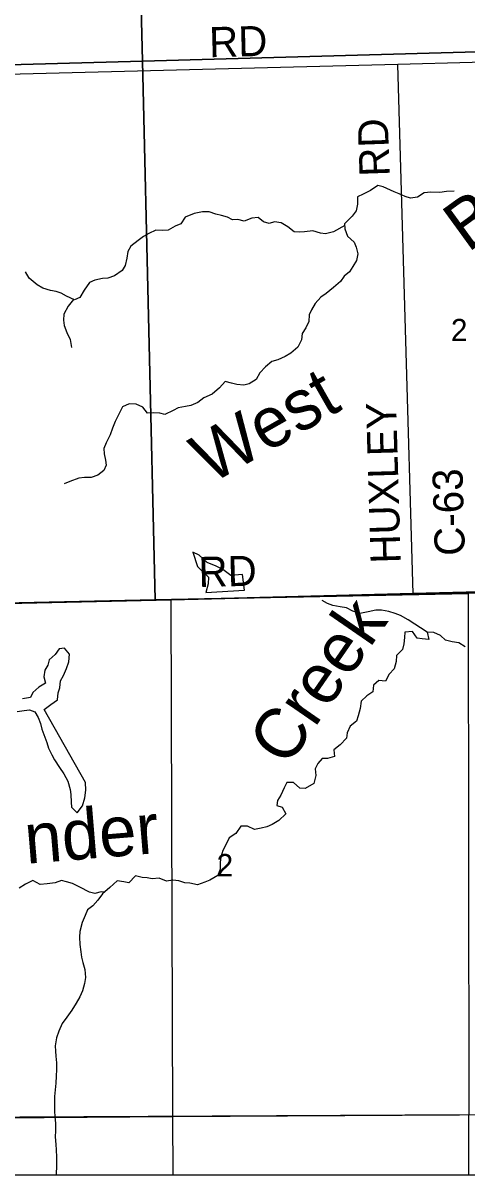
# Model space of a CAD drawing. Extents: x 0 to 34, y 0 to 22.
# Drawn here: x 8.101 to 8.938, y 14.007 to 16.179 of the extents above; entities that cross this region are included whole.
import ezdxf

# ---------------------------------------------------------------- set-up
doc = ezdxf.new("R2010")
doc.units = 0
for name, color, linetype in [('GM_X_Corporation', 7, 'Continuous'), ('GM_X_County_Road', 7, 'Continuous'), ('GM_X_County_Road_Text', 7, 'Continuous'), ('GM_X_Minor_Lake', 7, 'Continuous'), ('GM_X_Minor_River', 7, 'Continuous'), ('GM_X_Minor_River_Text', 7, 'Continuous'), ('GM_X_Section_Text', 7, 'Continuous'), ('GM_X_Township_Road', 7, 'Continuous')]:
    doc.layers.add(name, color=color, linetype=linetype)

msp = doc.modelspace()

# ---------------------------------------------------------------- linework, layer by layer
at = {"layer": 'GM_X_Corporation'}
msp.add_lwpolyline([(7.283, 17.3071), (7.2872, 17.1772), (7.2911, 17.0516), (7.2943, 16.935), (7.2998, 16.7507), (7.3046, 16.5913), (7.3049, 16.5704), (7.3097, 16.0633), (7.3129, 15.9614), (7.3375, 15.0689), (8.3803, 15.0917), (8.8365, 15.1033), (9.7895, 15.1275), (9.7895, 20.2375)], dxfattribs=at)
for points in [[(9.3117, 17.1675), (9.3404, 16.1359), (8.3266, 16.1074), (8.3006, 17.1406)], [(8.3006, 17.1406), (8.3266, 16.1074), (7.3183, 16.0795), (7.3111, 16.3358), (7.2941, 16.9623), (7.2894, 17.115)], [(8.3266, 16.1074), (9.3404, 16.1359), (9.3634, 15.1175), (8.9404, 15.1037), (8.3505, 15.0912)], [(7.3183, 16.0795), (8.3266, 16.1074), (8.3505, 15.0912), (7.8364, 15.0804), (7.3467, 15.0701), (7.331, 15.7019)], [(3.7367, 14.0069), (9.7895, 14.0069), (9.7895, 15.1275), (8.8365, 15.1033), (8.3803, 15.0917), (7.3375, 15.0689), (7.3134, 15.0684), (6.0746, 15.0468), (5.7825, 15.0418), (5.1362, 15.0301), (3.7218, 15.0051), (3.7359, 14.0555)], [(8.9404, 15.1037), (8.9421, 14.1205), (7.8527, 14.1143), (7.8364, 15.0804), (8.3505, 15.0912)], [(7.8543, 14.0069), (8.9421, 14.0069), (8.9421, 14.1205), (7.8527, 14.1143)]]:
    msp.add_lwpolyline(points, close=True, dxfattribs=at)
at = {"layer": 'GM_X_County_Road'}
for q in [(8.8082, 16.1011), (9.7895, 15.1269)]:
    msp.add_line((8.8367, 15.1028), q, dxfattribs=at)
for points in [[(9.7895, 16.1277), (8.8082, 16.1011), (7.3099, 16.0628)], [(7.3377, 15.0683), (8.3805, 15.0912), (8.8367, 15.1028)], [(7.332, 14.1088), (8.3836, 14.1171), (9.7895, 14.1254)]]:
    msp.add_lwpolyline(points, dxfattribs=at)
at = {"layer": 'GM_X_Minor_Lake'}
for points in [[(8.5187, 15.1098), (8.5152, 15.139), (8.4929, 15.1374), (8.4782, 15.1489), (8.4652, 15.1552), (8.4488, 15.1621), (8.4334, 15.1758), (8.4212, 15.1813), (8.4304, 15.1541), (8.4512, 15.1344), (8.4507, 15.1215), (8.4457, 15.1054)], [(8.4457, 15.1054), (8.5187, 15.1098)], [(8.1414, 14.8847), (8.1537, 14.894), (8.1664, 14.9026), (8.1677, 14.9159), (8.1709, 14.9255), (8.1722, 14.9388), (8.1773, 14.9488), (8.1835, 14.9622), (8.1875, 14.9748), (8.1887, 14.9889), (8.1794, 15.0001), (8.1692, 14.9988), (8.1618, 14.9884), (8.1503, 14.9783), (8.1478, 14.9684), (8.1423, 14.9588), (8.1406, 14.9466), (8.1439, 14.9345), (8.1311, 14.927), (8.1196, 14.9169), (8.1152, 14.9074), (8.1005, 14.9048)], [(8.0903, 14.8807), (8.1035, 14.8825), (8.1134, 14.8838), (8.1233, 14.8805), (8.1299, 14.8697), (8.1343, 14.8583), (8.1368, 14.8474), (8.1427, 14.8327), (8.1463, 14.8225), (8.1495, 14.8119), (8.1555, 14.7995), (8.1609, 14.7897), (8.1699, 14.7754), (8.1781, 14.7634), (8.1859, 14.7495), (8.1904, 14.7337), (8.1913, 14.7242), (8.192, 14.7098), (8.1925, 14.7003), (8.2033, 14.6895), (8.2137, 14.7033), (8.218, 14.7182), (8.2196, 14.7323), (8.2193, 14.7468)], [(8.2193, 14.7468), (8.1414, 14.8847)]]:
    msp.add_lwpolyline(points, dxfattribs=at)
at = {"layer": 'GM_X_Minor_River'}
for points in [[(8.9144, 15.8625), (8.9, 15.8619), (8.8872, 15.8597), (8.8701, 15.8606), (8.858, 15.8588), (8.8453, 15.8506), (8.8321, 15.8488), (8.8218, 15.852), (8.8107, 15.8572), (8.8012, 15.8608), (8.7805, 15.8706), (8.7702, 15.8727), (8.7568, 15.8634), (8.7425, 15.8566), (8.732, 15.8515), (8.7322, 15.8378), (8.7295, 15.8249), (8.7221, 15.8152), (8.7075, 15.8009), (8.7081, 15.7914), (8.7129, 15.7771), (8.7256, 15.7663), (8.7292, 15.7565), (8.7325, 15.744), (8.73, 15.7314), (8.7231, 15.7203), (8.7168, 15.7103), (8.7071, 15.7017), (8.6997, 15.6921), (8.687, 15.6805), (8.6728, 15.6692), (8.6631, 15.6626), (8.652, 15.6506), (8.6454, 15.6387), (8.641, 15.6291), (8.6405, 15.6162), (8.6346, 15.6047), (8.6276, 15.5935), (8.6267, 15.5817), (8.6194, 15.5683), (8.6064, 15.5566), (8.5955, 15.5504), (8.5816, 15.5444), (8.5706, 15.5408), (8.5583, 15.5307), (8.5479, 15.5198), (8.5406, 15.5068), (8.5279, 15.499), (8.5177, 15.4965), (8.5044, 15.4978), (8.4945, 15.5002), (8.4823, 15.5034), (8.4715, 15.4914), (8.4581, 15.4794), (8.442, 15.4723), (8.4311, 15.4637), (8.418, 15.4581), (8.4074, 15.4564), (8.3938, 15.4539), (8.3841, 15.4484), (8.369, 15.4413), (8.3595, 15.4437), (8.3466, 15.4443), (8.336, 15.4433), (8.3275, 15.4549), (8.3149, 15.4608), (8.3012, 15.4613), (8.2888, 15.4553), (8.2811, 15.4404), (8.2753, 15.4277), (8.2699, 15.4155), (8.2655, 15.4029), (8.2579, 15.3879), (8.2535, 15.3772), (8.2545, 15.3666), (8.257, 15.3552), (8.2579, 15.3454), (8.2535, 15.3354), (8.2423, 15.3264), (8.2299, 15.3224), (8.2174, 15.3222), (8.2068, 15.3208), (8.1895, 15.3144), (8.179, 15.3104)], [(8.7078, 15.7972), (8.687, 15.7857), (8.6719, 15.7816), (8.662, 15.7833), (8.6479, 15.7872), (8.6321, 15.7854), (8.6222, 15.7849), (8.6123, 15.7858), (8.6004, 15.7951), (8.5882, 15.8028), (8.5752, 15.8045), (8.5655, 15.8013), (8.5548, 15.8045), (8.5448, 15.8126), (8.5327, 15.8113), (8.518, 15.8057), (8.5062, 15.8089), (8.4964, 15.8083), (8.4868, 15.8135), (8.4758, 15.8163), (8.4651, 15.8187), (8.4521, 15.8231), (8.4396, 15.8232), (8.4238, 15.8202), (8.4069, 15.8135), (8.3991, 15.8004), (8.3879, 15.7964), (8.3751, 15.7889), (8.3638, 15.788), (8.352, 15.7889), (8.3385, 15.7826), (8.3283, 15.777), (8.3186, 15.7689), (8.3048, 15.7584), (8.2989, 15.7484), (8.2969, 15.7358), (8.2937, 15.7221), (8.2882, 15.7125), (8.274, 15.7027), (8.2612, 15.6983), (8.251, 15.6973), (8.2367, 15.6944), (8.2265, 15.6897), (8.2165, 15.6758), (8.2081, 15.6616), (8.1983, 15.6572), (8.1834, 15.6642), (8.1735, 15.6697), (8.1639, 15.6729), (8.1533, 15.6746), (8.1384, 15.6796), (8.1281, 15.6855), (8.1131, 15.6982), (8.1057, 15.7098)], [(8.1964, 15.6581), (8.1864, 15.6452), (8.1784, 15.6303), (8.1778, 15.6189), (8.1791, 15.609), (8.1839, 15.5958), (8.1902, 15.5822), (8.1928, 15.5675)], [(8.8631, 15.0305), (8.8274, 15.0541), (8.8133, 15.0618), (8.803, 15.0658), (8.7912, 15.0694), (8.7771, 15.0721), (8.7665, 15.0723), (8.7521, 15.069), (8.7363, 15.0657), (8.7233, 15.0704), (8.7115, 15.0762), (8.6993, 15.0783), (8.6852, 15.081), (8.6757, 15.0847), (8.6654, 15.0905)], [(8.9352, 15.0029), (8.9233, 15.0107), (8.9104, 15.012), (8.8979, 15.0152), (8.8882, 15.0241), (8.876, 15.0299), (8.8631, 15.0305), (8.8668, 15.0168), (8.8542, 15.0178), (8.8447, 15.0191), (8.8354, 15.0315), (8.8214, 15.0308), (8.8205, 15.0205), (8.8192, 15.0087), (8.8167, 14.9981), (8.8056, 14.9864), (8.805, 14.9754), (8.8011, 14.9613), (8.7918, 14.9512), (8.7849, 14.9382), (8.7723, 14.9391), (8.7623, 14.9306), (8.761, 14.918), (8.7498, 14.9102), (8.7386, 14.9001), (8.7369, 14.8868), (8.7334, 14.8727), (8.7298, 14.8627), (8.7179, 14.853), (8.7128, 14.8404), (8.7115, 14.8308), (8.6992, 14.8181), (8.6876, 14.8084), (8.6886, 14.7962), (8.6754, 14.7922), (8.6656, 14.7924), (8.6574, 14.7827), (8.6519, 14.7727), (8.6537, 14.7602), (8.6498, 14.745), (8.6333, 14.7359), (8.623, 14.7365), (8.6115, 14.7473), (8.599, 14.7471), (8.5938, 14.7371), (8.5877, 14.7229), (8.5814, 14.7129), (8.5797, 14.7034), (8.59, 14.7005), (8.597, 14.6881), (8.5836, 14.6754), (8.5709, 14.6679), (8.5611, 14.6635), (8.5505, 14.6607), (8.5377, 14.6585), (8.5247, 14.6648), (8.5118, 14.6645), (8.5026, 14.651), (8.4899, 14.6428), (8.4829, 14.6283), (8.4782, 14.6187), (8.4746, 14.6061), (8.4729, 14.5965), (8.4728, 14.5833), (8.4685, 14.5714), (8.4538, 14.5631), (8.4441, 14.5592), (8.4301, 14.5543), (8.4157, 14.5571), (8.4062, 14.5577), (8.3951, 14.5617), (8.3837, 14.563), (8.3717, 14.5612), (8.3579, 14.5667), (8.3451, 14.5653), (8.3356, 14.567), (8.3257, 14.5676), (8.3131, 14.5711), (8.3009, 14.558), (8.2914, 14.5597), (8.2788, 14.5617), (8.265, 14.5493), (8.2509, 14.5369), (8.2424, 14.5254), (8.2331, 14.5145), (8.223, 14.5071), (8.2186, 14.4964), (8.2128, 14.483), (8.2082, 14.4658), (8.2077, 14.4552), (8.2083, 14.4415), (8.2101, 14.4275), (8.2118, 14.4177), (8.2142, 14.4078), (8.2179, 14.3946), (8.2193, 14.3791), (8.2172, 14.368), (8.2133, 14.3543), (8.2082, 14.3428), (8.2012, 14.3309), (8.1935, 14.3178)], [(8.2548, 14.5403), (8.2489, 14.5407), (8.2365, 14.5374), (8.2266, 14.5403), (8.2082, 14.5498), (8.1944, 14.5564), (8.1834, 14.5599), (8.1739, 14.5621), (8.1618, 14.558), (8.1471, 14.5562), (8.1338, 14.5548), (8.1201, 14.5622), (8.1062, 14.5555), (8.0942, 14.5476)], [(8.1935, 14.3178), (8.1839, 14.3047), (8.1751, 14.2924), (8.1689, 14.2782), (8.1646, 14.2652), (8.1622, 14.2504), (8.1624, 14.2401), (8.1633, 14.2306), (8.1643, 14.2185), (8.1642, 14.2056), (8.1636, 14.1934), (8.1631, 14.1797), (8.1618, 14.1672), (8.1609, 14.155), (8.1608, 14.1402), (8.1607, 14.1273), (8.1613, 14.117), (8.1626, 14.1037), (8.1625, 14.0901), (8.1616, 14.0787), (8.163, 14.0643), (8.1639, 14.0544), (8.1646, 14.0404), (8.1645, 14.0255), (8.1637, 14.0069), (8.1637, 14.0069)]]:
    msp.add_lwpolyline(points, dxfattribs=at)
at = {"layer": 'GM_X_Township_Road'}
for p, q in [((8.3818, 14.6795), (8.3805, 15.0912)), ((8.3836, 14.1171), (8.3818, 14.6795)), ((8.3843, 14.0069), (8.3836, 14.1171))]:
    msp.add_line(p, q, dxfattribs=at)

# ---------------------------------------------------------------- texts
at = {"layer": 'GM_X_County_Road_Text'}
for s, rotation, p in [('RD', 1.4806, (8.4529, 16.1147)), ('RD', 91.9757, (8.7928, 15.8907)), ('HUXLEY', 91.6703, (8.8136, 15.1608)), ('C-63', 91.7153, (8.9347, 15.1753)), ('RD', 1.4825, (8.4329, 15.1155))]:
    msp.add_text(s, height=0.05682, rotation=rotation, dxfattribs=at).set_placement(p)
at = {"layer": 'GM_X_Minor_River_Text'}
for s, rotation, p in [('Branch', 35.9921, (8.9401, 15.7452)), ('West', 29.724, (8.4548, 15.3085)), ('Creek', 55.3631, (8.5991, 14.7736)), ('nder', 4.7074, (8.1076, 14.5936))]:
    msp.add_text(s, height=0.09473, rotation=rotation, dxfattribs=at).set_placement(p)
at = {"layer": 'GM_X_Section_Text'}
for p in [(8.9081, 15.5794), (8.4664, 14.5702)]:
    msp.add_text('2', height=0.0419, rotation=0, dxfattribs=at).set_placement(p)

doc.saveas('drawing.dxf')
